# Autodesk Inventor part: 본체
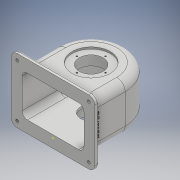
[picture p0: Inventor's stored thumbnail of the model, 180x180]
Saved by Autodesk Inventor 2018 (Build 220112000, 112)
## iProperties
Created: 2022-09
Part Number: 본체
Material: 일반
Document SubType Name: Modeling
Designer: home
Density: 1 g/cm^3
Appearance: 기본값
Mass: 792.206 g
Surface Area: 1125.07 cm^2
Volume: 293.41 cm^3
Author: home
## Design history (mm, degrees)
sketch "스케치1"
  geometry: L1 (-57, 0)-(-57, -64); L2 (57, 0)-(57, -64); L3 (57, -64)-(-57, -64); A1 r 57 centre (0, 0) between (57, 0) and (-57, 0); 1 further point
  constraints: 6 end point, 2 point on circle, 2 vertical, 1 centre point, 1 coincident, 1 perpendicular
  dimensions: "d0" = 57 radius of A1; "d1" = 64 distance of L1.start L1.end; "d2" = 64 distance of L2.start L2.end
extrude "돌출1" new body sketch "스케치1" distance "d3" = 78; taper "d4" = 0 deg
sketch "스케치2" dims "d175" = 1
  geometry: L1 (0, 0)-(0, 78) reference; L2 (0, 78)-(114, 78) reference; L3 (114, 78)-(114, 0) reference; L4 (114, 0)-(0, 0) reference; L5 (-13, 93)-(127, 93); L6 (127, 93)-(127, -15); L7 (127, -15)-(-13, -15); L8 (-13, -15)-(-13, 93); L9 (-13, 93)-(127, -15); L10 (127, 93)-(-13, -15); L11 (0, 0)-(0, 78) reference; L12 (0, 78)-(114, 78) reference; L13 (114, 78)-(114, 0) reference; L14 (114, 0)-(0, 0) reference; 2 further points
  constraints: 12 end point, 2 midpoint, 2 parallel, 1 horizontal, 1 perpendicular
  dimensions: "d5" = 140 distance of L6.end L7.end; "d6" = 108 distance of L5.end L6.end
  node "절단 모서리 투영1"
  node "절단 모서리 투영6"
feature "쉘1" dims "d7" = 5
extrude "돌출2" join sketch "스케치2" distance "d8" = 7; taper "d9" = 0 deg
fillet "모깎기1" dims "d12" = 14
fillet "모깎기2" dims "d13" = 10
sketch "스케치5"
  geometry: L1 (43, -57)-(43, 0) reference; L2 (-43, 0)-(-43, -57) reference; L3 (-70, -57)-(-43, -57) reference; L4 (43, -57)-(70, -57) reference; L5 (-43, -57)-(43, -57) reference; L6 (-70, -64)-(-70, -57) reference; L7 (70, -64)-(-70, -64) reference; L8 (70, -57)-(70, -64) reference; A1 r 43 centre (0, 0) between (43, 0) and (-43, 0) reference; 1 further point
  node "절단 모서리 투영4"
sketch "스케치8"
  geometry: 1 further point
hole "구멍2" diameter "d28" = 40; stored, may be unused: countersink angle "d32" = 90 deg, drill point angle "d34" = 0 deg; dims "d29" = 12, "d30" = 64, "d31" = 3, "d33" = 20, "d132" = 10, "d133" = 10
sketch "스케치9" dims "d37" = 24
  geometry: 3 further points
  constraints: 1 coincident, 1 vertical alignment, 2 other
hole "구멍3" sketch "스케치9" at (0, 24) diameter "d38" = 2.459; stored, may be unused: countersink angle "d42" = 90 deg, drill point angle "d44" = 0 deg; dims "d39" = 7, "d40" = 4, "d41" = 2, "d43" = 9
sketch "스케치10"
  geometry: C1 r 20 at (0, 0) reference; C2 r 31 at (0, 0); 1 further point
  constraints: 1 centre point, 1 coincident
  dimensions: "d48" = 31 radius of C2
extrude "돌출5" join sketch "스케치10" distance "d49" = 15; taper "d50" = 0 deg
hole "구멍4" diameter "d53" = 35; stored, may be unused: countersink angle "d57" = 90 deg, drill point angle "d59" = 0 deg; dims "d54" = 7, "d55" = 40, "d56" = 16, "d58" = 9, "d172" = 10, "d173" = 10
fillet "모깎기3" dims "d60" = 0.6
sketch "스케치12"
  geometry: 1 further point
node "작업 평면3"
sketch "스케치13"
  geometry: 1 further point
sketch "스케치14"
  geometry: 1 further point
sketch "스케치15"
  geometry: L1 (17, 93)-(103, 93) reference; L2 (60, 93)-(60, 54); C1 r 6 at (60, 54); 1 further point
  constraints: 2 end point, 1 centre point, 1 coincident, 1 midpoint, 1 vertical
  dimensions: "d75" = 39 distance of L2.start L2.end; "d76" = 6 radius of C1
extrude "돌출6" join sketch "스케치15" stored distance "d77" = 15; taper "d78" = 0 deg
hole "구멍6" diameter "d81" = 4.917; stored, may be unused: countersink angle "d85" = 90 deg, drill point angle "d87" = 0 deg; dims "d79" = 10, "d80" = 10, "d82" = 12, "d83" = 4, "d84" = 2, "d86" = 17.1
hole "구멍7" diameter "d90" = 4.917; stored, may be unused: countersink angle "d94" = 90 deg, drill point angle "d96" = 0 deg; dims "d88" = 10, "d89" = 10, "d91" = 12, "d92" = 4, "d93" = 2, "d95" = 17.1
hole "구멍8" diameter "d99" = 4.917; stored, may be unused: countersink angle "d103" = 90 deg, drill point angle "d105" = 0 deg; dims "d97" = 10, "d98" = 10, "d100" = 12, "d101" = 4, "d102" = 2, "d104" = 17.1
hole "구멍9" diameter "d108" = 4.917; stored, may be unused: countersink angle "d112" = 90 deg, drill point angle "d114" = 0 deg; dims "d106" = 10, "d107" = 10, "d109" = 12, "d110" = 4, "d111" = 2, "d113" = 17.1
fillet "모깎기5" dims "d115" = 3
hole "구멍10" diameter "d118" = 5.188; stored, may be unused: countersink angle "d122" = 90 deg, drill point angle "d124" = 0 deg; dims "d116" = 10, "d117" = 10, "d119" = 29, "d120" = 4, "d121" = 2, "d123" = 30
fillet "모깎기6" dims "d125" = 3
node "작업 평면4"
sketch "스케치16"
  geometry: C1 r 28 at (0, 0); 1 further point
  constraints: 1 centre point, 1 coincident
  dimensions: "d127" = 28 radius of C1
extrude "돌출7" join sketch "스케치16" distance "d128" = 15; taper "d129" = 30 deg
hole "구멍11" diameter "d134" = 40; stored, may be unused: countersink angle "d138" = 90 deg, drill point angle "d140" = 0 deg; dims "d130" = 10, "d131" = 10, "d135" = 29, "d136" = 4, "d137" = 2, "d139" = 20
hole "구멍12" diameter "d143" = 2.459; stored, may be unused: countersink angle "d147" = 90 deg, drill point angle "d149" = 0 deg; dims "d141" = 10, "d142" = 10, "d144" = 7, "d145" = 4, "d146" = 2, "d148" = 9
sketch "스케치17"
  geometry: L1 (50, -54)-(0, -54) reference; L2 (59.644, -57)-(76, -57) reference; L3 (79, -60)-(79, -64) reference; L4 (79, -64)-(-29, -64) reference; L5 (-29, -64)-(-29, -60) reference; L6 (-26, -57)-(-9.644, -57) reference; L7 (0, -54)-(0, 0) reference; L8 (50, 0)-(0, 0) reference; L9 (50, 0)-(50, -54) reference; L10 (-29, -64)-(-29, -47); L11 (-14, 0)-(-14, -54) reference; L12 (-14, -47)-(-14, -8); L13 (-14, -47)-(25, -47); A1 r 3 centre (76, -60) between (79, -60) and (76, -57) reference; A2 r 3 centre (-26, -60) between (-26, -57) and (-29, -60) reference; 2 further points
  constraints: 6 end point, 2 point on line, 1 horizontal, 1 vertical, 3 other
  dimensions: "d153" = 17 distance of L4.end L10.end; "d154" = 39 distance of L12.start L12.end; "d155" = 39 distance of L12.start L13.end
feature "엠보싱1" sketch "스케치17" dims "d156" = 0.5, "d157" = 0
fillet "모깎기7" dims "d158" = 3
fillet "모깎기8" dims "d159" = 9
fillet "모깎기9" dims "d160" = 9
sketch "스케치18"
  geometry: C1 r 24 at (0, 0); C2 r 1.23 at (0, 24) reference; 2 further points
  constraints: 2 coincident, 1 centre point
  dimensions: "d161" = 24 radius of C1
hole "구멍13" sketch "스케치18" at (0, 24) diameter "d162" = 2.459; stored, may be unused: countersink angle "d166" = 90 deg, drill point angle "d168" = 118 deg; dims "d163" = 7, "d164" = 4, "d165" = 2, "d167" = 9
fillet "모깎기10" dims "d174" = 1
chamfer "모따기1" distance "d175" = 1; stored, may be unused: second distance "d176" = 2, angle "d177" = 45 deg
fillet "모깎기11" dims "d178" = 3
node "솔리드1"
pattern_circular "원형 패턴1" dims angle "d46" = 360 deg
pattern_circular "원형 패턴3" dims angle "d151" = 360 deg
pattern_circular "원형 패턴4" dims angle "d170" = 360 deg
node "절단 모서리 투영5"
other parameters: "d74" = -124, "d126" = 14
